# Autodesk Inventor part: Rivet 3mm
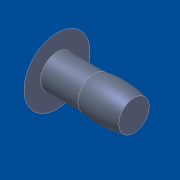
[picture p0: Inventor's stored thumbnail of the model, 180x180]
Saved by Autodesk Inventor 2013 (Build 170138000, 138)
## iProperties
Shininess: 20.0
Length Units: 11269
Angle Units: 11279
Time Units: 11290
Mass Units: 11283
Length Display Precision: 3
Angle Display Precision: 2
Created: 2001-04
Part Number: Rivet 3mm
Material: Standard
Document SubType Name: Modellieren
Designer: dl
Density: 1 g/cm^3
Density: 0.0
Volumn: 0.0
Area: 0.0
PropertySet Name: Model Information
Control State: 0
Master: False
Checked Out: False
Author: dl
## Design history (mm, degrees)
body "Solid1"
sketch "Sketch2"
  geometry: C1 r 1 at (0, 0) reference; 1 further point
  constraints: 1 coincident
revolve "Revolution1" stored, may be unused: angle "d8" = 90 deg
hole "Hole1" sketch "Sketch2" diameter "d10" = 1.5; stored, may be unused: countersink angle "d14" = 60 deg, drill point angle "d16" = 118 deg; dims "d11" = 6, "d12" = 4, "d13" = 2, "d15" = 5
sketch "Sketch1"
  geometry: L1 (0, 4.762)-(0, 5.762); L2 (1, 7.762)-(1, 6.262); L3 (1, 6.262)-(4.4, 6.262); L4 (8, 6.146)-(8, 4.762); L5 (8, 4.762)-(0, 4.762); A1 r 6.195 centre (5.95, 4.037) between (1, 7.762) and (0, 5.762); A2 r 8 centre (5.95, -1.587) between (8, 6.146) and (4.4, 6.262)
  constraints: 10 end point, 4 point on circle, 2 centre point, 2 parallel, 1 horizontal, 1 perpendicular, 1 vertical
  dimensions: "d0" = 1 distance of L1.start L1.end; "d1" = 3 vertical distance of L1.start L2.start; "d2" = 1.5 distance from line of L4.end L3; "d3" = 1 distance between parallel lines of L2 L1; "d4" = 3.4 distance of L2.end L3.end; "d5" = 8 radius of A2; "d6" = 8 distance of L4.end L1.start; "d7" = 1.55 horizontal distance of L3.end A2.centre; "d17" = 0 horizontal distance of A1.centre A2.centre
